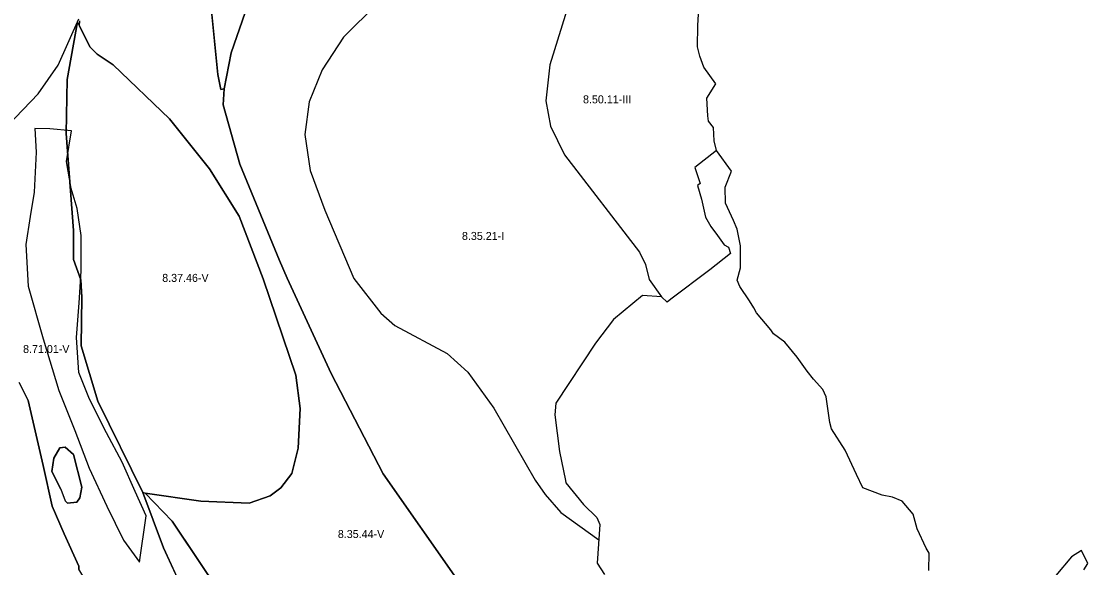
# Model space of a CAD drawing. Extents: x -547623 to -533936, y -1096714 to -1086523.
# Drawn here: x -539983 to -538651, y -1092360 to -1091678 of the extents above; entities that cross this region are included whole.
import ezdxf

# ---------------------------------------------------------------- set-up
doc = ezdxf.new("R2010")
doc.units = 0
for name, color, linetype in [('Vrstva 27', 7, 'Continuous'), ('Vrstva 28', 7, 'Continuous'), ('Vrstva 29', 7, 'Continuous')]:
    doc.layers.add(name, color=color, linetype=linetype)

msp = doc.modelspace()

# ---------------------------------------------------------------- linework, layer by layer
at = {"layer": 'Vrstva 28'}
for p, q in [((-539757.5, -1091541.5), (-539737.5, -1091744)), ((-539926, -1091750), (-539913, -1091678)), ((-539913, -1091678), (-539910.5, -1091683)), ((-539910.5, -1091683), (-539910, -1091677)), ((-539897.5, -1091709.5), (-539910.5, -1091683)), ((-539910.5, -1091683), (-539897.5, -1091709.5)), ((-539888.5, -1091718.5), (-539897.5, -1091709.5)), ((-539897.5, -1091709.5), (-539888.5, -1091718.5)), ((-539868.5, -1091732), (-539888.5, -1091718.5)), ((-539888.5, -1091718.5), (-539868.5, -1091732)), ((-539798, -1091799.5), (-539868.5, -1091732)), ((-539868.5, -1091732), (-539798, -1091799.5)), ((-539927, -1091817.5), (-539926, -1091750)), ((-539737.5, -1091744), (-539734, -1091762.5)), ((-539734, -1091762.5), (-539729.5, -1091762)), ((-539729.5, -1091762), (-539731, -1091782)), ((-539731, -1091782), (-539710, -1091856)), ((-539748, -1091862), (-539798, -1091799.5)), ((-539798, -1091799.5), (-539748, -1091862)), ((-539918, -1091939), (-539927, -1091817.5)), ((-539710, -1091856), (-539660.5, -1091976.5)), ((-539711, -1091921), (-539748, -1091862)), ((-539748, -1091862), (-539711, -1091921)), ((-539681, -1091999.5), (-539711, -1091921)), ((-539711, -1091921), (-539681, -1091999.5)), ((-539918, -1091975), (-539918, -1091939)), ((-539909, -1092000.5), (-539918, -1091975)), ((-539660.5, -1091976.5), (-539651, -1091998.5)), ((-539907.5, -1092022), (-539909, -1092000.5)), ((-539640, -1092119.5), (-539681, -1091999.5)), ((-539681, -1091999.5), (-539640, -1092119.5)), ((-539651, -1091998.5), (-539596, -1092117.5)), ((-539908.5, -1092083), (-539907.5, -1092022)), ((-539887.5, -1092152), (-539908.5, -1092083)), ((-539634.5, -1092161.5), (-539640, -1092119.5)), ((-539640, -1092119.5), (-539634.5, -1092161.5)), ((-539596, -1092117.5), (-539531, -1092243)), ((-539986, -1092129), (-539974.5, -1092151.5)), ((-539974.5, -1092151.5), (-539956, -1092232.5)), ((-539831.5, -1092266.5), (-539887.5, -1092152)), ((-539637, -1092211), (-539634.5, -1092161.5)), ((-539634.5, -1092161.5), (-539637, -1092211)), ((-539935, -1092210.5), (-539942.5, -1092223.5)), ((-539942.5, -1092223.5), (-539935, -1092210.5)), ((-539928.5, -1092209.5), (-539935, -1092210.5)), ((-539935, -1092210.5), (-539928.5, -1092209.5)), ((-539918, -1092219), (-539928.5, -1092209.5)), ((-539928.5, -1092209.5), (-539918, -1092219)), ((-539907.5, -1092259.5), (-539918, -1092219)), ((-539918, -1092219), (-539907.5, -1092259.5)), ((-539645, -1092242.5), (-539637, -1092211)), ((-539637, -1092211), (-539645, -1092242.5)), ((-539956, -1092232.5), (-539944.5, -1092283.5)), ((-539942.5, -1092223.5), (-539945, -1092240)), ((-539945, -1092240), (-539942.5, -1092223.5)), ((-539933.9, -1092262), (-539945, -1092240)), ((-539659, -1092260.5), (-539645, -1092242.5)), ((-539645, -1092242.5), (-539659, -1092260.5)), ((-539531, -1092243), (-539393.5, -1092439)), ((-539910, -1092273), (-539907.5, -1092259.5)), ((-539907.5, -1092259.5), (-539910, -1092273)), ((-539914, -1092278.5), (-539910, -1092273)), ((-539910, -1092273), (-539914, -1092278.5)), ((-539805.5, -1092335.5), (-539831.5, -1092266.5)), ((-539831.5, -1092266.5), (-539828.5, -1092267)), ((-539828.5, -1092267), (-539831.5, -1092266.5)), ((-539828.5, -1092267), (-539794.5, -1092302)), ((-539794.5, -1092302), (-539828.5, -1092267)), ((-539828.5, -1092267), (-539759, -1092277)), ((-539759, -1092277), (-539828.5, -1092267)), ((-539698.5, -1092279.5), (-539672, -1092270.5)), ((-539672, -1092270.5), (-539698.5, -1092279.5)), ((-539672, -1092270.5), (-539659, -1092260.5)), ((-539659, -1092260.5), (-539672, -1092270.5)), ((-539944.5, -1092283.5), (-539929.5, -1092318)), ((-539925.5, -1092279.5), (-539928.6, -1092276.6)), ((-539925.5, -1092279.5), (-539914, -1092278.5)), ((-539914, -1092278.5), (-539925.5, -1092279.5)), ((-539759, -1092277), (-539698.5, -1092279.5)), ((-539698.5, -1092279.5), (-539759, -1092277)), ((-539794.5, -1092302), (-539712, -1092425.5)), ((-539712, -1092425.5), (-539794.5, -1092302)), ((-539929.5, -1092318), (-539911.5, -1092358.5)), ((-539779.5, -1092391.5), (-539805.5, -1092335.5)), ((-539911.5, -1092358.5), (-539911.5, -1092362))]:
    msp.add_line(p, q, dxfattribs=at)
for points in [[(-539169.5, -1092577), (-539185.5, -1092571), (-539287, -1092514.5), (-539311.5, -1092507), (-539332, -1092498.5), (-539347, -1092488.5), (-539393.5, -1092439), (-539531, -1092243), (-539596, -1092117.5), (-539651, -1091998.5), (-539660.5, -1091976.5), (-539710, -1091856), (-539731, -1091782), (-539729.5, -1091762), (-539721, -1091717), (-539651, -1091515), (-539633, -1091443), (-539625, -1091372.5), (-539631.5, -1091334.5), (-539656, -1091243.5), (-539657, -1091239.4)], [(-539235.5, -1091465), (-539235.5, -1091468.5), (-539272.5, -1091570.5), (-539322.5, -1091732), (-539327.5, -1091777), (-539322, -1091808.5), (-539304.5, -1091844.5), (-539210.5, -1091966), (-539203, -1091981.5), (-539198.5, -1092000), (-539183, -1092021.8)], [(-539651, -1091515), (-539721, -1091717), (-539729.5, -1091762), (-539734, -1091762.5), (-539737.5, -1091744), (-539757.5, -1091541.5)], [(-539471.7, -1091576.9), (-539496, -1091613), (-539580.5, -1091697.5), (-539607, -1091738), (-539623.5, -1091778), (-539629, -1091819), (-539622, -1091864), (-539604, -1091913.5), (-539567.5, -1091999), (-539534, -1092042), (-539516.5, -1092057.5), (-539451, -1092092.5), (-539425, -1092116), (-539392.5, -1092161), (-539341, -1092251), (-539328.5, -1092269), (-539309, -1092291.5), (-539261.5, -1092325.3)], [(-538849.2, -1092363.8), (-538848.7, -1092342.2), (-538852.4, -1092336), (-538863.7, -1092311.6), (-538868.5, -1092293.2), (-538882.3, -1092277.3), (-538894.3, -1092272.2), (-538907.3, -1092269.6), (-538931.3, -1092260.6), (-538939.5, -1092243.9), (-538953.7, -1092213.5), (-538970.7, -1092186.8), (-538972.6, -1092178.9), (-538977.5, -1092146.7), (-538981.4, -1092137.6), (-538993.2, -1092124.8), (-539001.1, -1092114.5), (-539013.7, -1092097.2), (-539028.9, -1092078.5), (-539043.1, -1092068.1), (-539046.3, -1092063.1), (-539064.6, -1092041.6), (-539067.7, -1092035.5), (-539073.3, -1092026.8), (-539085.2, -1092008.8), (-539088.7, -1092001.1), (-539084.2, -1091985.5), (-539084.6, -1091958), (-539088.6, -1091937.4), (-539093.3, -1091926.4), (-539103.2, -1091904.7), (-539103.7, -1091884.8), (-539095.5, -1091864.9), (-539114.4, -1091839.1), (-539117.1, -1091826.8), (-539118.1, -1091810), (-539124.3, -1091802.1), (-539125.2, -1091795.4), (-539126.5, -1091773.5), (-539115.1, -1091755.5), (-539130.1, -1091734.7), (-539135.3, -1091721.2), (-539138, -1091709.5), (-539137.7, -1091682.6), (-539134.9, -1091633.7)], [(-539828.5, -1092267), (-539759, -1092277), (-539698.5, -1092279.5), (-539672, -1092270.5), (-539659, -1092260.5), (-539645, -1092242.5), (-539637, -1092211), (-539634.5, -1092161.5), (-539640, -1092119.5), (-539681, -1091999.5), (-539711, -1091921), (-539748, -1091862), (-539798, -1091799.5), (-539868.5, -1091732), (-539888.5, -1091718.5), (-539897.5, -1091709.5), (-539910.5, -1091683), (-539913, -1091678), (-539926, -1091750), (-539927, -1091817.5), (-539918, -1091939), (-539918, -1091975), (-539909, -1092000.5), (-539907.5, -1092022), (-539908.5, -1092083), (-539887.5, -1092152), (-539831.5, -1092266.5), (-539828.5, -1092267)], [(-538849.2, -1092363.8), (-538848.7, -1092342.2), (-538852.4, -1092336), (-538863.7, -1092311.6), (-538868.5, -1092293.2), (-538882.3, -1092277.3), (-538894.3, -1092272.2), (-538907.3, -1092269.6), (-538931.3, -1092260.6), (-538939.5, -1092243.9), (-538953.7, -1092213.5), (-538970.7, -1092186.8), (-538972.6, -1092178.9), (-538977.5, -1092146.7), (-538981.4, -1092137.6), (-538993.2, -1092124.8), (-539001.1, -1092114.5), (-539013.7, -1092097.2), (-539028.9, -1092078.5), (-539043.1, -1092068.1), (-539046.3, -1092063.1), (-539064.6, -1092041.6), (-539067.7, -1092035.5), (-539073.3, -1092026.8), (-539085.2, -1092008.8), (-539088.7, -1092001.1), (-539084.2, -1091985.5), (-539084.6, -1091958), (-539088.6, -1091937.4), (-539093.3, -1091926.4), (-539103.2, -1091904.7), (-539103.7, -1091884.8), (-539095.5, -1091864.9), (-539114.4, -1091839.1), (-539141.6, -1091860.3), (-539134.9, -1091880.2), (-539138.2, -1091882.8), (-539133, -1091899.7), (-539128.2, -1091922.4), (-539121.3, -1091934), (-539113.2, -1091945.2), (-539104.8, -1091956.9), (-539099.3, -1091959.9), (-539096.7, -1091967.5), (-539122.7, -1091988.1), (-539171.4, -1092024.8), (-539176.1, -1092028.3), (-539183, -1092021.8), (-539206.8, -1092020), (-539243.1, -1092050.3), (-539265.8, -1092079.6), (-539315, -1092154.6), (-539316.6, -1092169.2), (-539310.7, -1092215), (-539303.2, -1092251.3), (-539302.6, -1092254.2), (-539280.6, -1092281.5), (-539263.9, -1092297.6), (-539260.2, -1092306.4), (-539263.4, -1092354.6), (-539254.3, -1092368.8)], [(-539911.5, -1092362), (-539911.5, -1092358.5), (-539929.5, -1092318), (-539944.5, -1092283.5), (-539956, -1092232.5), (-539974.5, -1092151.5), (-539986, -1092129)], [(-539190.2, -1093026.6), (-539191.8, -1093024.9), (-539192.6, -1093024), (-539214.6, -1093000), (-539255, -1092956), (-539331.5, -1092885), (-539356, -1092866), (-539431, -1092815), (-539548.5, -1092744.5), (-539642.5, -1092677.5), (-539754, -1092580.5), (-539880, -1092414), (-539911.5, -1092362), (-539911.5, -1092358.5), (-539929.5, -1092318), (-539944.5, -1092283.5), (-539956, -1092232.5), (-539974.5, -1092151.5), (-539986, -1092129)], [(-539945, -1092240), (-539933.9, -1092262), (-539928.6, -1092276.6)], [(-539544.5, -1092656), (-539393.5, -1092739.5), (-539327, -1092784.5), (-539225.5, -1092868.5), (-539219, -1092876.5), (-539223, -1092856.5), (-539220, -1092843), (-539204, -1092828.5), (-539177.1, -1092812.9), (-539215.5, -1092777), (-539294, -1092709.5), (-539353.5, -1092671), (-539467, -1092614.5), (-539579, -1092547), (-539669.5, -1092470.5), (-539712, -1092425.5), (-539794.5, -1092302), (-539828.5, -1092267), (-539831.5, -1092266.5), (-539805.5, -1092335.5), (-539779.5, -1092391.5), (-539681.5, -1092533.5), (-539581, -1092630.5), (-539544.5, -1092656)], [(-538655.5, -1092362.9), (-538650.5, -1092355.1), (-538658.2, -1092338.6), (-538670.7, -1092346.5), (-538690.2, -1092370.2)]]:
    msp.add_lwpolyline(points, dxfattribs=at)
at = {"layer": 'Vrstva 29'}
for points in [[(-540221.2, -1091623.2), (-540230.3, -1091690.3), (-540242.9, -1091760.6), (-540094.8, -1091787.5), (-540000, -1091807.8), (-539962.1, -1091768.2), (-539937.2, -1091732.2), (-539911.5, -1091674.3)], [(-539827.2, -1092295.3), (-539840.8, -1092264.9), (-539857.1, -1092228.6), (-539876.8, -1092191.8), (-539897.8, -1092149.6), (-539911.3, -1092116.4), (-539914.3, -1092072.8), (-539910.8, -1092029.1), (-539908.5, -1091989.6), (-539908.3, -1091945.1), (-539913.6, -1091911.5), (-539921.1, -1091886.6), (-539926.6, -1091852.5), (-539920.4, -1091814.5), (-539947.5, -1091811.8), (-539966.1, -1091811.5), (-539964.5, -1091841.2), (-539967.1, -1091890.8), (-539972, -1091921.5), (-539977.6, -1091956.5), (-539974.8, -1092008.3), (-539955.9, -1092074.1), (-539936.3, -1092139), (-539916.5, -1092189), (-539898.6, -1092236.1), (-539876.3, -1092283.3), (-539855.4, -1092325.8), (-539835.4, -1092353.3), (-539827.2, -1092295.3)]]:
    msp.add_lwpolyline(points, dxfattribs=at)

# ---------------------------------------------------------------- texts
at = {"layer": 'Vrstva 27'}
for s, p in [('8.50.11-III', (-539281.2, -1091780)), ('8.35.21-I', (-539432.5, -1091950.7)), ('8.37.46-V', (-539807.1, -1092003.1)), ('8.71.01-V', (-539981, -1092092)), ('8.35.44-V', (-539587.6, -1092323.2))]:
    msp.add_text(s, height=10, dxfattribs=at).set_placement(p)

doc.saveas('drawing.dxf')
